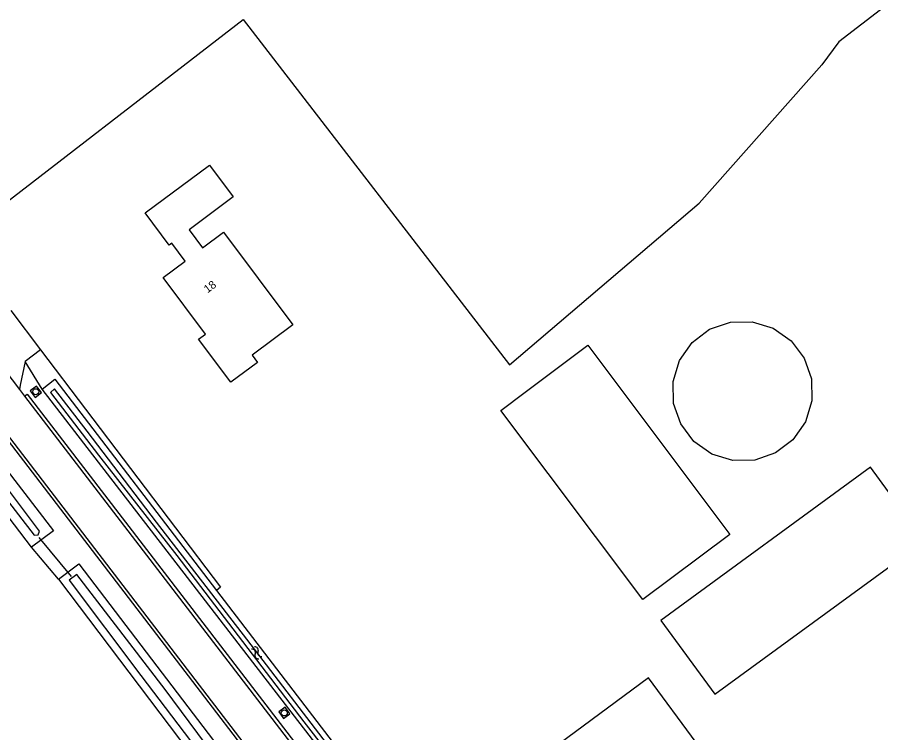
# Model space of a CAD drawing. Extents: x 136000 to 141000, y 400494 to 402006.
# Drawn here: x 136343.1 to 136451, y 401670.5 to 401759.9 of the extents above; entities that cross this region are included whole.
import ezdxf

# ---------------------------------------------------------------- set-up
doc = ezdxf.new("R2010")
doc.units = 0
for name, color, linetype in [('gg-afsc-draadraster', 7, 'Continuous'), ('gg-afsc-hekwerk', 7, 'Continuous'), ('gg-afsc-lijn draadraster', 7, 'Continuous'), ('gg-anno-huisnummerreeks BGT', 7, 'Continuous'), ('gg-bbg-bijgebouw', 7, 'Continuous'), ('gg-bbg-gedigitaliseerde bijgebouw', 7, 'Continuous'), ('gg-bbg-hoofdgebouw', 7, 'Continuous'), ('gg-bbg-opslagtank', 7, 'Continuous'), ('gg-knt-bronhoudergrens', 7, 'Continuous'), ('gg-knt-verharding', 7, 'Continuous'), ('gg-kntw-bovenkant insteek waterloop', 7, 'Continuous'), ('gg-kntw-waterlijn', 7, 'Continuous'), ('gg-kwrk-duiker nz buis', 7, 'Continuous'), ('gt-grn-groengrens', 7, 'Continuous'), ('gt-symb-rioolschacht', 7, 'Continuous'), ('gt-symb-watersymbool', 7, 'Continuous')]:
    doc.layers.add(name, color=color, linetype=linetype)

# ---------------------------------------------------------------- blocks, each defined once
blk = doc.blocks.new('gt0-WA')
at = {"layer": 'gt-symb-watersymbool'}
for centre, start, end in [((-0.32, 0.02), 28.0725, 151.9275), ((0.43, 0.42), 208.0725, 331.9275), ((-0.32, -0.43), 28.0725, 151.9275), ((0.43, -0.03), 208.0725, 331.9275)]:
    blk.add_arc(centre, 0.425, start, end, dxfattribs=at)
blk = doc.blocks.new('gt0-RS')
at = {"layer": 'gt-symb-rioolschacht'}
blk.add_lwpolyline([(-0.5, -0.5), (0.5, -0.5), (0.5, 0.5), (-0.5, 0.5)], close=True, dxfattribs=at)
blk.add_circle((0, 0), 0.375, dxfattribs=at)

msp = doc.modelspace()

# ---------------------------------------------------------------- linework, layer by layer
at = {"layer": 'gg-afsc-draadraster'}
msp.add_lwpolyline([(136336.02, 401732.4), (136371.34, 401759.63), (136404.62, 401716.46)], dxfattribs=at)
at = {"layer": 'gg-afsc-hekwerk'}
for p, q in [((136342.33, 401723.25), (136346.05, 401718.35)), ((136346.05, 401718.35), (136368.52, 401688.7))]:
    msp.add_line(p, q, dxfattribs=at)
at = {"layer": 'gg-afsc-lijn draadraster'}
msp.add_lwpolyline([(136336.02, 401732.4), (136371.34, 401759.63), (136404.62, 401716.46)], dxfattribs=at)
at = {"layer": 'gg-bbg-bijgebouw'}
msp.add_lwpolyline([(136413.72, 401658.77), (136427.93, 401669.3), (136421.95, 401677.37), (136407.74, 401666.84), (136413.72, 401658.77)], dxfattribs=at)
at = {"layer": 'gg-bbg-gedigitaliseerde bijgebouw'}
msp.add_line((136406.55, 401713.06), (136414.37, 401718.93), dxfattribs=at)
for points in [[(136414.37, 401718.93), (136432.1, 401695.29), (136421.25, 401687.15)], [(136421.25, 401687.15), (136403.52, 401710.79), (136406.55, 401713.06)], [(136430.25, 401675.33), (136456.41, 401694.47), (136449.67, 401703.68), (136423.51, 401684.55), (136430.25, 401675.33)]]:
    msp.add_lwpolyline(points, dxfattribs=at)
at = {"layer": 'gg-bbg-hoofdgebouw'}
msp.add_lwpolyline([(136361.37, 401727.41), (136364.1, 401729.43), (136362.42, 401731.69), (136362.09, 401731.44), (136359.09, 401735.45), (136367.12, 401741.43), (136370.1, 401737.45), (136364.6, 401733.34), (136366.28, 401731.09), (136368.9, 401733.04), (136377.55, 401721.47), (136372.46, 401717.67), (136373.12, 401716.79), (136369.79, 401714.3), (136365.76, 401719.67), (136366.65, 401720.33), (136361.37, 401727.41)], dxfattribs=at)
at = {"layer": 'gg-bbg-opslagtank'}
msp.add_lwpolyline([(136440, 401707.13), (136437.81, 401705.48), (136435.23, 401704.59), (136432.49, 401704.54), (136429.87, 401705.33), (136427.63, 401706.9), (136425.98, 401709.09), (136425.09, 401711.67), (136425.04, 401714.41), (136425.84, 401717.03), (136427.4, 401719.27), (136429.59, 401720.92), (136432.18, 401721.81), (136434.91, 401721.86), (136437.53, 401721.06), (136439.77, 401719.49), (136441.42, 401717.31), (136442.31, 401714.72), (136442.36, 401711.99), (136441.57, 401709.37), (136440, 401707.13)], dxfattribs=at)
at = {"layer": 'gg-knt-bronhoudergrens'}
msp.add_line((136404.62, 401716.46), (136428.27, 401736.67), dxfattribs=at)
msp.add_lwpolyline([(136462.83, 401772.77), (136451.49, 401761.24), (136445.71, 401756.81), (136443.61, 401753.97), (136428.27, 401736.67)], dxfattribs=at)
at = {"layer": 'gg-knt-verharding'}
for p, q in [((136336.95, 401721.87), (136343.4, 401713.39)), ((136346.05, 401718.35), (136344.13, 401716.88)), ((136344.13, 401716.88), (136343.51, 401713.92)), ((136343.51, 401713.92), (136343.4, 401713.39)), ((136343.4, 401713.39), (136344.03, 401712.57)), ((136344.03, 401712.57), (136397.56, 401642.86))]:
    msp.add_line(p, q, dxfattribs=at)
for points in [[(136398.16, 401633.71), (136339.94, 401709.66), (136301.62, 401759.9)], [(136398.45, 401633.95), (136340.23, 401709.89), (136301.9, 401760.16)], [(136344.03, 401712.57), (136344.35, 401712.8), (136397.89, 401643.11), (136397.56, 401642.86)]]:
    msp.add_lwpolyline(points, dxfattribs=at)
at = {"layer": 'gg-kntw-bovenkant insteek waterloop'}
for p, q in [((136344.92, 401693.72), (136316.55, 401730.57)), ((136346.22, 401713.43), (136347.81, 401714.67)), ((136347.81, 401714.67), (136368.01, 401688.3)), ((136348.28, 401689.7), (136373.8, 401656)), ((136368.01, 401688.3), (136390.18, 401659.35))]:
    msp.add_line(p, q, dxfattribs=at)
for points in [[(136318.34, 401733.9), (136319.24, 401732.71), (136347.67, 401695.76), (136344.92, 401693.72)], [(136390.18, 401659.35), (136388.85, 401658.2), (136346.22, 401713.43)], [(136348.28, 401689.7), (136350.83, 401691.61), (136379.91, 401653.43)]]:
    msp.add_lwpolyline(points, dxfattribs=at)
at = {"layer": 'gg-kntw-waterlijn'}
for points in [[(136293.25, 401763.38), (136295.5, 401759.66), (136300.97, 401752.6), (136314.11, 401735.33), (136337.8, 401704.81), (136345.26, 401695.19), (136345.73, 401695.25), (136345.89, 401695.7), (136342.02, 401700.87), (136324.35, 401723.68), (136302.49, 401752.48), (136294.01, 401763.89), (136293.25, 401763.38)], [(136347.3, 401713.01), (136353.26, 401705.21), (136363.06, 401692.65), (136378.93, 401671.9), (136389.04, 401658.84), (136389.52, 401659.26), (136382.81, 401667.82), (136371.8, 401682.22), (136360.51, 401696.81), (136351.84, 401708.2), (136347.8, 401713.5), (136347.3, 401713.01)], [(136378.87, 401652.63), (136375.74, 401656.86), (136361.6, 401675.91), (136350.55, 401690.29), (136349.62, 401689.58), (136358.55, 401677.66), (136376.27, 401654.41), (136376.28, 401653.77), (136375.64, 401653.24)]]:
    msp.add_lwpolyline(points, dxfattribs=at)
at = {"layer": 'gg-kwrk-duiker nz buis'}
msp.add_line((136349.89, 401690.02), (136345.87, 401694.93), dxfattribs=at)
at = {"layer": 'gt-grn-groengrens'}
for p, q in [((136346.22, 401713.43), (136344.13, 401716.88)), ((136348.28, 401689.7), (136344.92, 401693.72)), ((136368.52, 401688.7), (136368.01, 401688.3))]:
    msp.add_line(p, q, dxfattribs=at)

# ---------------------------------------------------------------- block references
at = {"layer": 'gt-symb-rioolschacht'}
for p, rotation in [((136345.44, 401713.12), 37.523171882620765), ((136376.48, 401673), 35.67760208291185)]:
    msp.add_blockref('gt0-RS', p, dxfattribs=dict(at, rotation=rotation))
at = {"layer": 'gt-symb-watersymbool', "rotation": -52.76334102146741}
msp.add_blockref('gt0-WA', (136372.99, 401680.55), dxfattribs=at)

# ---------------------------------------------------------------- texts
at = {"layer": 'gg-anno-huisnummerreeks BGT'}
msp.add_text('18', height=1, rotation=36.7, dxfattribs=at).set_placement((136366.89, 401725.4))

doc.saveas('drawing.dxf')
